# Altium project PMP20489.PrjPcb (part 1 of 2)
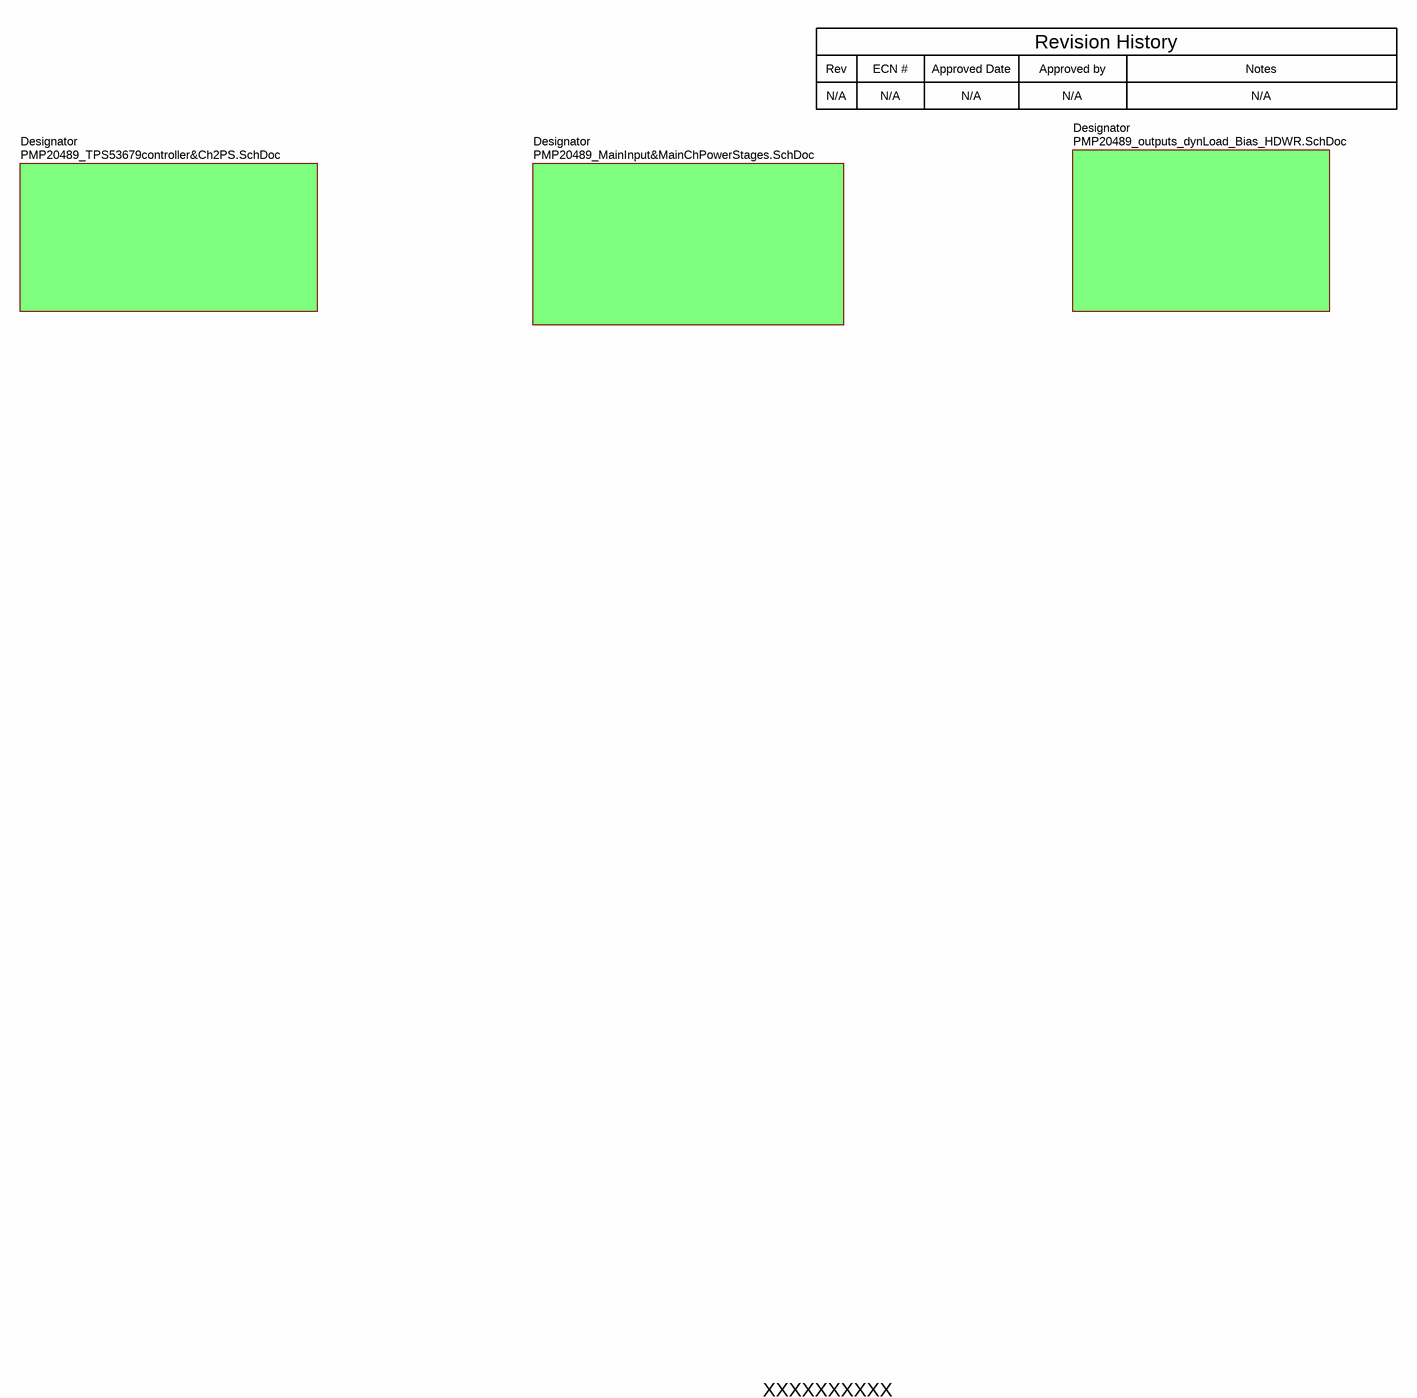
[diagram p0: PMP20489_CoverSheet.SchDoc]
TID: N/A; TechSupport: http://www.ti.com/support; SCH_Rev: A; PRJ_Title: TPS53679 & CSD95490 5+2 4.5-13.2Vin; PRJ_Number: PMP20489; PRJ_Engineer: Josh Mandelcorn; PRJ_Customer: Public Release; PCB_Rev: A; PCB_Layout: Krypton Solutions/RS; EVM_orderable: No; CopyrightYear: 2016
4 sheets, 332 parts. Net scope: flat (ports and power ports of the same name join across sheets).
Board file: PMP20489_PCB.PcbDoc
Sheets:
  PMP20489_CoverSheet.SchDoc
    Designator = PMP20489_TPS53679controller&Ch2PS.SchDoc
    Designator = PMP20489_MainInput&MainChPowerStages.SchDoc
    Designator = PMP20489_outputs_dynLoad_Bias_HDWR.SchDoc

## Sheet PMP20489_CoverSheet.SchDoc
size 431 x 279 mm; Date: Not shown in title block; ApprovedBy: Not shown in title block; CheckedBy: Not shown in title block; Author: Not shown in title block; CompanyName: Not shown in title block; Engineer: Not shown in title block; Organization: Not shown in title block; Address1: Not shown in title block; Address2: Not shown in title block; Address3: Not shown in title block; Address4: Not shown in title block; DocumentNumber: 1; Revision: Use project parameter SCH_Rev; SheetNumber: 1; SheetTotal: 4; PageSetup: Record=PageOptions¦CenterHorizontal=True¦CenterVertical=True¦PrintScale=1.00¦XCorrection=1.00¦YCorrection=1.00¦PrintKind=0¦BorderSize=5000000¦LeftOffset=0¦BottomOffset=0¦Orientation=2¦PaperLength=1000¦PaperWidth=1000¦Scale=100¦PaperSource=15¦PrintQuality=600¦MediaType=1¦DitherType=10¦PaperKind=Letter¦PrintScaleMode=1

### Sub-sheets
Designator = PMP20489_TPS53679controller&Ch2PS.SchDoc: no entries
Designator = PMP20489_MainInput&MainChPowerStages.SchDoc: no entries
Designator = PMP20489_outputs_dynLoad_Bias_HDWR.SchDoc: no entries

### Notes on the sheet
- Rev
- N/A
- ECN #
- Approved Date
- Approved by
- Revision History
- Notes
- XXXXXXXXXX

## Sheet PMP20489_TPS53679controller&Ch2PS.SchDoc
size 431 x 279 mm; Date: Not shown in title block; ApprovedBy: Not shown in title block; CheckedBy: Not shown in title block; Author: Not shown in title block; CompanyName: Not shown in title block; Engineer: Not shown in title block; Organization: Not shown in title block; Address1: Not shown in title block; Address2: Not shown in title block; Address3: Not shown in title block; Address4: Not shown in title block; DocumentNumber: 2; Revision: Use project parameter SCH_Rev; SheetNumber: 2; SheetTotal: 4; PageSetup: Record=PageOptions¦CenterHorizontal=True¦CenterVertical=True¦PrintScale=1.00¦XCorrection=1.00¦YCorrection=1.00¦PrintKind=0¦BorderSize=5000000¦LeftOffset=0¦BottomOffset=0¦Orientation=2¦PaperLength=1000¦PaperWidth=1000¦Scale=100¦PaperSource=15¦PrintQuality=600¦MediaType=1¦DitherType=10¦PaperKind=Letter¦PrintScaleMode=1
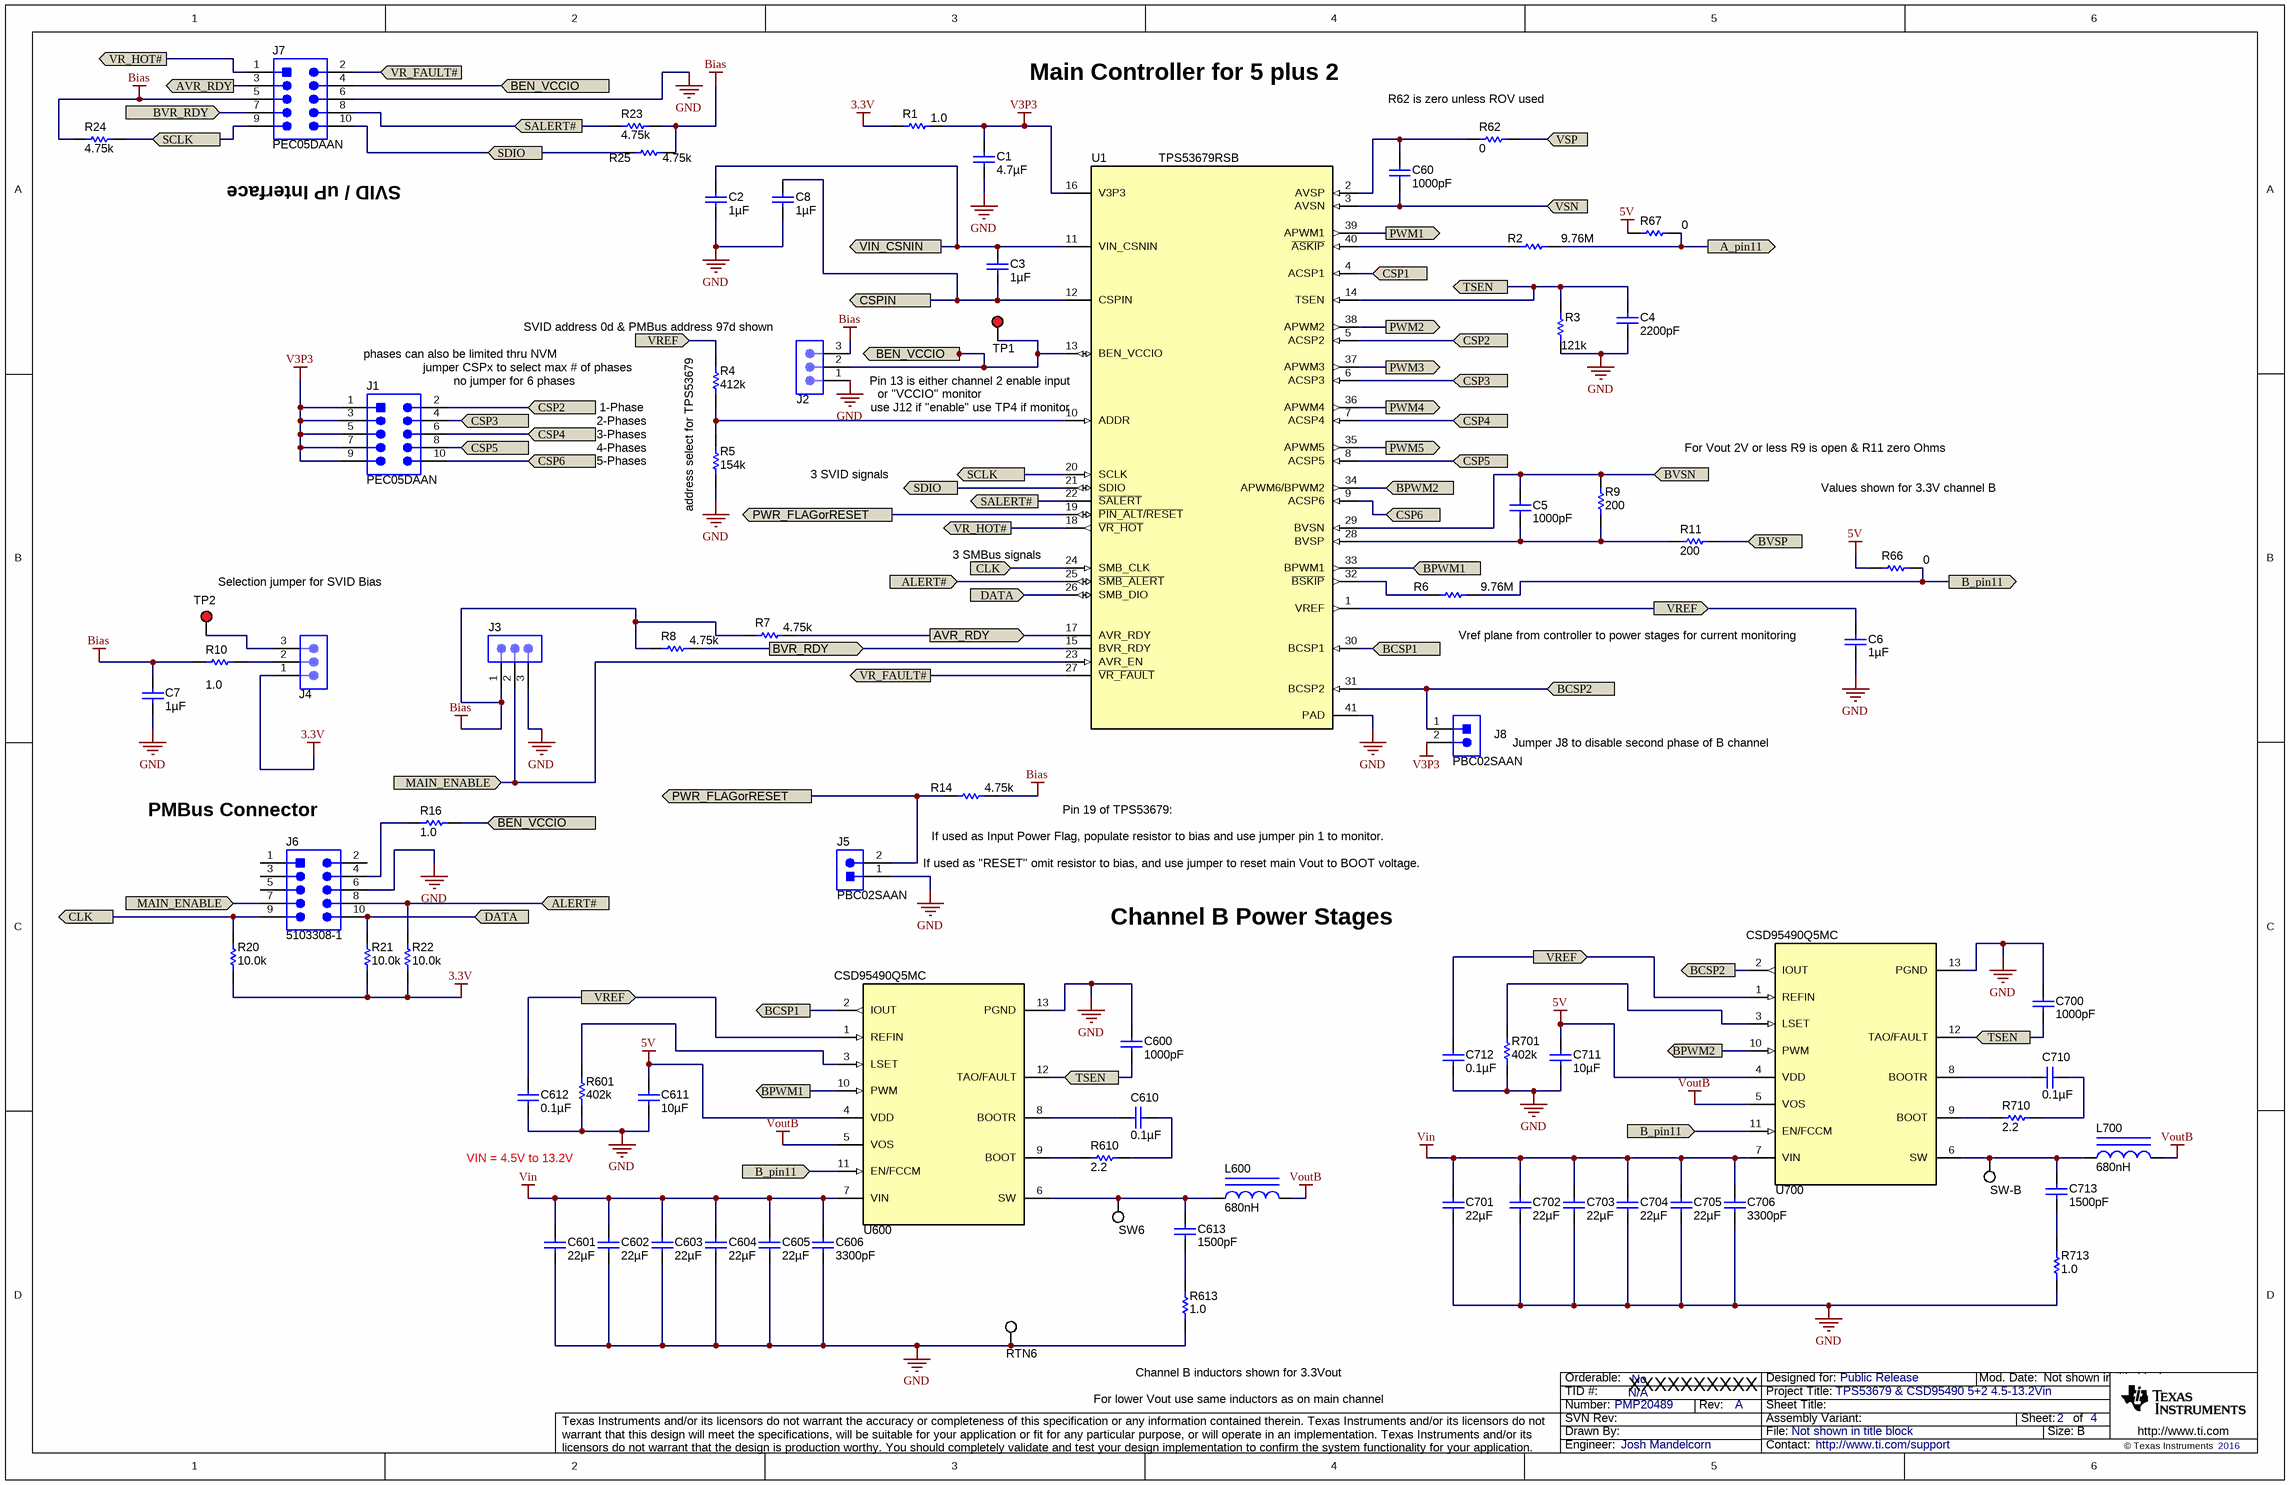
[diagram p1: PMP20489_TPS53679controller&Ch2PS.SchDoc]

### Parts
C1  ValueDisplayed: 4.7µF  [0402]  (hidden comment: GRM155R61A475M)
C2  ValueDisplayed: 1µF  [0603]  (hidden comment: C1608X5R1E105K080AC)
C3  ValueDisplayed: 1µF  [0402]  (hidden comment: C1005X7S1A105K050BC)
C4  ValueDisplayed: 2200pF  [0402]  (hidden comment: C1005X7R1H222K)
C5  ValueDisplayed: 1000pF  [0402L]  (hidden comment: C1005X7R1H102K)
C6  ValueDisplayed: 1µF  [0402]  (hidden comment: C1005X7S1A105K050BC)
C7  ValueDisplayed: 1µF  [0603]  (hidden comment: C1608X5R1E105K080AC)
C8  ValueDisplayed: 1µF  [0603]  (hidden comment: C1608X5R1E105K080AC)
C60  ValueDisplayed: 1000pF  [0402]  (hidden comment: C1005X7R1H102K)
C600  ValueDisplayed: 1000pF  [0402]  (hidden comment: C1005C0G1E102J)
C601  ValueDisplayed: 22µF  [1210]  (hidden comment: C3225X5R1C226M)
C602  ValueDisplayed: 22µF  [1210]  (hidden comment: C3225X5R1C226M)
C603  ValueDisplayed: 22µF  [1210]  (hidden comment: C3225X5R1C226M)
C604  ValueDisplayed: 22µF  [1210]  (hidden comment: C3225X5R1C226M)
C605  ValueDisplayed: 22µF  [1210]  (hidden comment: C3225X5R1C226M)
C606  ValueDisplayed: 3300pF  [0402]  (hidden comment: C1005X7R1H332K)
C610  ValueDisplayed: 0.1µF  [0402]  (hidden comment: GRM155R61E104KA87D)
C611  ValueDisplayed: 10µF  [0603L]  (hidden comment: C0603C106M9PACTU)
C612  ValueDisplayed: 0.1µF  [0402]  (hidden comment: GRM155R61C104KA88D)
C613  ValueDisplayed: 1500pF  [0805_HV]  (hidden comment: 08051C152KAT2A)
C700  ValueDisplayed: 1000pF  [0402]  (hidden comment: C1005C0G1E102J)
C701  ValueDisplayed: 22µF  [1210]  (hidden comment: C3225X5R1C226M)
C702  ValueDisplayed: 22µF  [1210]  (hidden comment: C3225X5R1C226M)
C703  ValueDisplayed: 22µF  [1210]  (hidden comment: C3225X5R1C226M)
C704  ValueDisplayed: 22µF  [1210]  (hidden comment: C3225X5R1C226M)
C705  ValueDisplayed: 22µF  [1210]  (hidden comment: C3225X5R1C226M)
C706  ValueDisplayed: 3300pF  [0402]  (hidden comment: C1005X7R1H332K)
C710  ValueDisplayed: 0.1µF  [0402]  (hidden comment: GRM155R61E104KA87D)
C711  ValueDisplayed: 10µF  [0603L]  (hidden comment: C0603C106M9PACTU)
C712  ValueDisplayed: 0.1µF  [0402]  (hidden comment: GRM155R61C104KA88D)
C713  ValueDisplayed: 1500pF  [0805_HV]  (hidden comment: 08051C152KAT2A)
J1  PEC05DAAN  [CONN_PEC05DAAN]
J2  PBC03SAAN  [PBC03SAAN]  (value not drawn)
J3  PBC03SAAN  [PBC03SAAN]  (value not drawn)
J4  PBC03SAAN  [PBC03SAAN]  (value not drawn)
J5  PBC02SAAN  [Sullins_PBC02SAAN]
J6  5103308-1  [CONN_5103308-1]
J7  PEC05DAAN  [CONN_PEC05DAAN]
J8  PBC02SAAN  [Sullins_PBC02SAAN]
L600  ValueDisplayed: 680nH  [XAL1010]  (hidden comment: XAL1010-681MEB)
L700  ValueDisplayed: 680nH  [XAL1010]  (hidden comment: XAL1010-681MEB)
R1  ValueDisplayed: 1.0  [0402]  (hidden comment: CRCW04021R00JNED)
R2  ValueDisplayed: 9.76M  [0402]  (hidden comment: CRCW04029M76FKED)
R3  ValueDisplayed: 121k  [0402]  (hidden comment: CRCW0402121KFKED)
R4  ValueDisplayed: 412k  [0402]  (hidden comment: CRCW0402412KFKED)
R5  ValueDisplayed: 154k  [0402]  (hidden comment: CRCW0402154KFKED)
R6  ValueDisplayed: 9.76M  [0402]  (hidden comment: CRCW04029M76FKED)
R7  ValueDisplayed: 4.75k  [0402]  (hidden comment: CRCW04024K75FKED)
R8  ValueDisplayed: 4.75k  [0402]  (hidden comment: CRCW04024K75FKED)
R9  ValueDisplayed: 200  [0402]  (hidden comment: CRCW0402200RFKED)
R10  ValueDisplayed: 1.0  [0402]  (hidden comment: CRCW04021R00JNED)
R11  ValueDisplayed: 200  [0402]  (hidden comment: CRCW0402200RFKED)
R14  ValueDisplayed: 4.75k  [0402]  (hidden comment: CRCW04024K75FKED)
R16  value 1.0  [0402]  (hidden comment: CRCW04021R00JNED)
R20  value 10.0k  [0402]  (hidden comment: CRCW040210K0FKED)
R21  value 10.0k  [0402]  (hidden comment: CRCW040210K0FKED)
R22  value 10.0k  [0402]  (hidden comment: CRCW040210K0FKED)
R23  ValueDisplayed: 4.75k  [0402]  (hidden comment: CRCW04024K75FKED)
R24  ValueDisplayed: 4.75k  [0402]  (hidden comment: CRCW04024K75FKED)
R25  ValueDisplayed: 4.75k  [0402]  (hidden comment: CRCW04024K75FKED)
R62  ValueDisplayed: 0  [0402]  (hidden comment: CRCW04020000Z0ED)
R66  ValueDisplayed: 0  [0402]  (hidden comment: RC0402JR-070RL)
R67  ValueDisplayed: 0  [0402]  (hidden comment: RC0402JR-070RL)
R601  ValueDisplayed: 402k  [0402]  (hidden comment: CRCW0402402KFKED)
R610  value 2.2  [0402]  (hidden comment: CRCW04022R20JNED)
R613  value 1.0  [1206]  (hidden comment: CRM1206-JW-1R0ELF)
R701  ValueDisplayed: 402k  [0402]  (hidden comment: CRCW0402402KFKED)
R710  value 2.2  [0402]  (hidden comment: CRCW04022R20JNED)
R713  value 1.0  [1206]  (hidden comment: CRM1206-JW-1R0ELF)
RTN6  5016  [Testpoint_Keystone_Compact]  (value not drawn)
SW6  5015  [Testpoint_Keystone_Miniature]  (value not drawn)
SW-B  5015  [Testpoint_Keystone_Miniature]  (value not drawn)
TP1  5000  [Keystone5000]  (value not drawn)
TP2  5000  [Keystone5000]  (value not drawn)
U1  TPS53679RSB  [RSB0040E]
U600  CSD95490Q5MC  [DMC0012A]
U700  CSD95490Q5MC  [DMC0012A]

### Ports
A_pin11, ALERT#, ALERT# (in), AVR_RDY, AVR_RDY (out), B_pin11, BCSP1, BCSP1 (out), BCSP2, BCSP2 (out), BEN_VCCIO, BPWM1, BPWM2, BVR_RDY, BVR_RDY (out), BVSN, BVSP, CLK, CSP1 (in), CSP2, CSP2 (in), CSP3, CSP3 (in), CSP4, CSP5, CSP6, CSPIN, DATA, DATA (in), MAIN_ENABLE, MAIN_ENABLE (in), PWM1 (out), PWM2 (out), PWM3 (out), PWM4 (out), PWM5 (out), PWR_FLAGorRESET, SALERT#, SCLK, SDIO, TSEN, VIN_CSNIN, VR_FAULT#, VR_HOT#, VREF, VSN (in), VSP (in)

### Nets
3.3V: J4.1 R1.1 R20.2 R21.2 R22.2
5V: C611.1 C711.1 R66.1 R67.1 U600.4(VDD) U700.4(VDD)
Bias: C7.1 J2.3 J3.1 J7.5 R7.2 R8.2 R10.1 R14.1 R23.1 R24.2 R25.1
GND: C1.2 C2.2 C4.2 C6.2 C7.2 C8.2 C600.1 C601.2 C602.2 C603.2 C604.2 C605.2 C606.2 C611.2 C612.2 C700.1 C701.2 C702.2 C703.2 C704.2 C705.2 C706.2 C711.2 C712.2 J2.1 J3.3 J5.1 J6.6 J7.6 R3.1 R5.1 R601.1 R613.1 R701.1 R713.1 RTN6.1 U1.41(PAD) U600.13(PGND) U700.13(PGND)
V3P3: C1.1 J1.1 J1.3 J1.5 J1.7 J1.9 J8.2 R1.2 U1.16(V3P3)
Vin: C601.1 C602.1 C603.1 C604.1 C605.1 C606.1 C701.1 C702.1 C703.1 C704.1 C705.1 C706.1 U600.7(VIN) U700.7(VIN)
VoutB: L600.2 L700.2 U600.5(VOS) U700.5(VOS)
A_pin11: R2.2 R67.2 ; port A_pin11
ALERT#: J6.8 R22.1 U1.25(~{SMB_ALERT}) ; port ALERT#
AVR_RDY: J7.3 R7.1 U1.17(AVR_RDY) ; port AVR_RDY
B_pin11: R6.2 R66.2 U600.11(EN/FCCM) U700.11(EN/FCCM) ; port B_pin11
BCSP1: U1.30(BCSP1) U600.2(IOUT) ; port BCSP1
BCSP2: J8.1 U1.31(BCSP2) U700.2(IOUT) ; port BCSP2
BEN_VCCIO: J2.2 J7.4 R16.2 TP1.1 U1.13(BEN_VCCIO) ; port BEN_VCCIO
BPWM1: U1.33(BPWM1) U600.10(PWM) ; port BPWM1
BPWM2: U1.34(APWM6/BPWM2) U700.10(PWM) ; port BPWM2
BVR_RDY: J7.7 R8.1 U1.15(BVR_RDY) ; port BVR_RDY
BVSN: C5.1 R9.2 U1.29(BVSN) ; port BVSN
BVSP: R11.2 ; port BVSP
CLK: J6.9 R20.1 U1.24(SMB_CLK) ; port CLK
CSP1: U1.4(ACSP1) ; port CSP1
CSP2: J1.2 U1.5(ACSP2) ; port CSP2
CSP3: J1.4 U1.6(ACSP3) ; port CSP3
CSP4: J1.6 U1.7(ACSP4) ; port CSP4
CSP5: J1.8 U1.8(ACSP5) ; port CSP5
CSP6: J1.10 U1.9(ACSP6) ; port CSP6
CSPIN: C3.2 C8.1 U1.12(CSPIN) ; port CSPIN
DATA: J6.10 R21.1 U1.26(SMB_DIO) ; port DATA
MAIN_ENABLE: J3.2 J6.7 U1.23(AVR_EN) ; port MAIN_ENABLE
PWM1: U1.39(APWM1) ; port PWM1
PWM2: U1.38(APWM2) ; port PWM2
PWM3: U1.37(APWM3) ; port PWM3
PWM4: U1.36(APWM4) ; port PWM4
PWM5: U1.35(APWM5) ; port PWM5
PWR_FLAGorRESET: J5.2 R14.2 U1.19(~{PIN_ALT}/~{RESET}) ; port PWR_FLAGorRESET
SALERT#: J7.8 R23.2 U1.22(~{SALERT}) ; port SALERT#
SCLK: J7.9 R24.1 U1.20(SCLK) ; port SCLK
SDIO: J7.10 R25.2 U1.21(SDIO) ; port SDIO
TSEN: C4.1 C600.2 C700.2 R3.2 U1.14(TSEN) U600.12(TAO/FAULT) U700.12(TAO/FAULT) ; port TSEN
VIN_CSNIN: C2.1 C3.1 U1.11(VIN_CSNIN) ; port VIN_CSNIN
VR_FAULT#: J7.2 U1.27(~{VR_FAULT}) ; port VR_FAULT#
VR_HOT#: J7.1 U1.18(~{VR_HOT}) ; port VR_HOT#
VREF: C6.1 C612.1 C712.1 R4.2 U1.1(VREF) U600.1(REFIN) U700.1(REFIN) ; port VREF
VSN: C60.2 U1.3(AVSN) ; port VSN
VSP: R62.2 ; port VSP
NetC5_2: C5.2 R9.1 R11.1 U1.28(BVSP)
NetC60_1: C60.1 R62.1 U1.2(AVSP)
NetC610_1: C610.1 U600.8(BOOTR)
NetC610_2: C610.2 R610.1
NetC613_1: C613.1 L600.1 SW6.1 U600.6(SW)
NetC613_2: C613.2 R613.2
NetC710_1: C710.1 U700.8(BOOTR)
NetC710_2: C710.2 R710.1
NetC713_1: C713.1 L700.1 SW-B.1 U700.6(SW)
NetC713_2: C713.2 R713.2
NetJ4_2: J4.2 R10.2
NetJ4_3: J4.3 TP2.1
NetJ6_4: J6.4 R16.1
NetR2_1: R2.1 U1.40(~{ASKIP})
NetR4_1: R4.1 R5.2 U1.10(ADDR)
NetR6_1: R6.1 U1.32(~{BSKIP})
NetR601_2: R601.2 U600.3(LSET)
NetR610_2: R610.2 U600.9(BOOT)
NetR701_2: R701.2 U700.3(LSET)
NetR710_2: R710.2 U700.9(BOOT)

Not connected (* = marked no-connect by the designer): J6 1 2 3 5

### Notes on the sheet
- Main Controller for 5 plus 2
- (near R62) R62 is zero unless ROV used
- SVID / uP Interface
- (near J1) phases can also be limited thru NVM
- (near J1) jumper CSPx to select max # of phases
- (near R4) SVID address 0d & PMBus address 97d shown
- (near J1) no jumper for 6 phases
- 3-Phases
- 2-Phases
- 1-Phase
- address select for TPS53679
- or "VCCIO" monitor
- (near U1) Pin 13 is either channel 2 enable input
- (near U1) use J12 if "enable" use TP4 if monitor
- 4-Phases
- 5-Phases
- 3 SVID signals
- For Vout 2V or less R9 is open & R11 zero Ohms
- Values shown for 3.3V channel B
- (near U1) 3 SMBus signals
- (near TP2) Selection jumper for SVID Bias
- Vref plane from controller to power stages for current monitoring
- (near J8) Jumper J8 to disable second phase of B channel
- (near J6) PMBus Connector
- Pin 19 of TPS53679:
- If used as Input Power Flag, populate resistor to bias and use jumper pin 1 to monitor.
- (near J5) If used as "RESET" omit resistor to bias, and use jumper to reset main Vout to BOOT voltage.
- Channel B Power Stages
- VIN = 4.5V to 13.2V
- (near R613) Channel B inductors shown for 3.3Vout
- XXXXXXXXXX
- For lower Vout use same inductors as on main channel

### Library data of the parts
C1 = GRM155R61A475M: CAP, CERM, 4.7 µF, 10 V, +/- 20%, X5R, 0402; Manufacturer: MuRata; Polarized: N; CompType: Capacitor; Value: 4.7uF; U/M: EA; Cap_F: 0.0000047; Tolerance_%: 20; Value1: Unknown; VDC_V: 10; Value2: 10V; TaMin_C: -55; TaMax_C: 85; SizeArea_mm2: 0.5; SizeAreaWB_mm2: 3; SizeX_mm: 1; SizeZ_mm: 0.6; AEC Category: Q200
C2 C7 C8 = C1608X5R1E105K080AC: CAP, CERM, 1 µF, 25 V, +/- 10%, X5R, 0603; Manufacturer: TDK; Polarized: N; CompType: Capacitor; Value: 1uF; U/M: EA; Cap_F: 0.000001; Tolerance_%: 10; Value1: Unknown; VDC_V: 25; Value2: 25V; TaMin_C: -55; TaMax_C: 85; SizeArea_mm2: 1.28; SizeAreaWB_mm2: 4.68; SizeX_mm: 1.6; SizeY_mm: 0.8; SizeZ_mm: 1; AEC Category: Q200
C3 C6 = C1005X7S1A105K050BC: CAP, CERM, 1 µF, 10 V, +/- 10%, X7S, 0402; Manufacturer: TDK; Polarized: N; CompType: Capacitor; Value: 1uF; U/M: EA; Cap_F: 0.000001; Tolerance_%: 10; ESR_ohm: 0.011416; Value1: 0.011416 ohm; Value2: 10V; IRMS_A: 1.483; TaMin_C: -55; TaMax_C: 125; SizeArea_mm2: 0.5; SizeAreaWB_mm2: 3; SizeX_mm: 1; SizeZ_mm: 0.6; AEC Category: Q200
C4 = C1005X7R1H222K: CAP, CERM, 2200 pF, 50 V, +/- 10%, X7R, 0402; Manufacturer: TDK; Polarized: N; CompType: Capacitor; Value: 2200pF; U/M: EA; Cap_F: 0.0000000022; Tolerance_%: 10; ESR_ohm: 0.1433; Value1: 0.1433 ohm; VDC_V: 50; Value2: 50V; TaMin_C: -55; TaMax_C: 125
C5 = C1005X7R1H102K: CAP, CERM, 1000 pF, 50 V, +/- 10%, X7R, 0402; Manufacturer: TDK; Polarized: N; CompType: Capacitor; Value: 1000pF; U/M: EA; Cap_F: 0.000000001; Tolerance_%: 10; ESR_ohm: 0.2381; Value1: 0.2381 ohm; VDC_V: 50; Value2: 50V; TaMin_C: -55; TaMax_C: 125; Cap_Case: 0402
C60 = C1005X7R1H102K: CAP, CERM, 1000 pF, 50 V, +/- 10%, X7R, 0402; Manufacturer: TDK; Polarized: N; CompType: Capacitor; Value: 1000pF; U/M: EA; Cap_F: 0.000000001; Tolerance_%: 10; ESR_ohm: 0.2381; Value1: 0.2381 ohm; VDC_V: 50; Value2: 50V; TaMin_C: -55; TaMax_C: 125
C600 C700 = C1005C0G1E102J: CAP, CERM, 1000 pF, 25 V, +/- 5%, C0G/NP0, 0402; Manufacturer: TDK; Polarized: N; CompType: Capacitor; Value: 1000pF; U/M: EA; Cap_F: 0.000000001; Tolerance_%: 5; Value1: Unknown; VDC_V: 25; Value2: 25V; TaMin_C: -55; TaMax_C: 125
C601-C605 C701-C705 = C3225X5R1C226M: CAP, CERM, 22 µF, 16 V, +/- 20%, X5R, 1210; Manufacturer: TDK; Polarized: N; CompType: Capacitor; Value: 22uF; U/M: EA; Cap_F: 0.000022; Tolerance_%: 20; ESR_ohm: 0.002; Value1: 0.002 ohm; VDC_V: 16; Value2: 16V; IRMS_A: 3.5; TaMin_C: -55; TaMax_C: 85
C606 C706 = C1005X7R1H332K: CAP, CERM, 3300 pF, 50 V, +/- 10%, X7R, 0402; Manufacturer: TDK; Polarized: N; CompType: Capacitor; Value: 3300pF; U/M: EA; Cap_F: 0.0000000033; Tolerance_%: 10; ESR_ohm: 0.12; Value1: 0.12 ohm; VDC_V: 50; Value2: 50V; TaMin_C: -55; TaMax_C: 125
C610 C710 = GRM155R61E104KA87D: CAP, CERM, 0.1 µF, 25 V, +/- 10%, X5R, 0402; Manufacturer: MuRata; Polarized: N; CompType: Capacitor; Value: 0.1uF; U/M: EA; Cap_F: 0.0000001; Tolerance_%: 10; Value1: Unknown; VDC_V: 25; Value2: 25V; TaMin_C: -55; TaMax_C: 85; SizeArea_mm2: 0.5; SizeAreaWB_mm2: 3; SizeX_mm: 1; SizeZ_mm: 0.6; AEC Category: Q200
C611 C711 = C0603C106M9PACTU: CAP, CERM, 10 µF, 6.3 V, +/- 20%, X5R, 0603; Manufacturer: Kemet; Polarized: N; CompType: Capacitor; Value: 10uF; U/M: EA; Cap_F: 0.00001; Tolerance_%: 20; ESR_ohm: 0.004; Value1: 0.004 ohm; VDC_V: 6.3; Value2: 6.3V; IRMS_A: 8.9; TaMin_C: -55; TaMax_C: 85; Cap_Case: 0603; SizeArea_mm2: 1.28; SizeAreaWB_mm2: 4.68; SizeX_mm: 1.6; SizeY_mm: 0.8; SizeZ_mm: 1; AEC Category: Q200
C612 C712 = GRM155R61C104KA88D: CAP, CERM, 0.1 µF, 16 V, +/- 10%, X5R, 0402; Manufacturer: MuRata; Polarized: N; CompType: Capacitor; Value: 0.1uF; U/M: EA; Cap_F: 0.0000001; Tolerance_%: 10; Value1: Unknown; VDC_V: 16; Value2: 16V; TaMin_C: -55; TaMax_C: 85; SizeArea_mm2: 0.5; SizeAreaWB_mm2: 3; SizeX_mm: 1; SizeZ_mm: 0.6; AEC Category: Q200
C613 C713 = 08051C152KAT2A: CAP, CERM, 1500 pF, 100 V, +/- 10%, X7R, 0805; Manufacturer: AVX; Polarized: N; CompType: Capacitor; Value: 1500pF; U/M: EA; Cap_F: 0.0000000015; Tolerance_%: 10; ESR_ohm: 0.229; Value1: 0.229 ohm; VDC_V: 100; Value2: 100V; TaMin_C: -55; TaMax_C: 125; Cap_Case: 0805; SizeArea_mm2: 2.5; SizeAreaWB_mm2: 6.75; SizeX_mm: 2; SizeY_mm: 1.25; SizeZ_mm: 1.45; AEC Category: Q200
J1 J7 = PEC05DAAN: Header, 100mil, 5x2, Tin, TH; Manufacturer: Sullins Connector Solutions; SymbolCreator: a0412235; Pitch_mm: 2.54; Gender: Male; Shrouded: N; Row_Count: 2; Current_A: 3; Voltage_V: 1800; Cert_UL: Y
J2-J4 = PBC03SAAN: Header, 100mil, 3x1, Gold, TH; Manufacturer: Sullins Connector Solutions
J5 J8 = PBC02SAAN: Header, 100mil, 2x1, Gold, TH; Manufacturer: Sullins Connector Solutions; SymbolCreator: a0412235; Pitch_mm: 2.54; Gender: Male; Shrouded: N; Row_Count: 1; Current_A: 3; Voltage_V: 1800; Cert_UL: Y
J6 = 5103308-1: Header (shrouded), 100mil, 5x2, Gold, TH; Manufacturer: TE Connectivity; SymbolCreator: a0412235
L600 L700 = XAL1010-681MEB: Inductor, Shielded, Composite, 680 nH, 36 A, 0.00087 ohm, SMD; Manufacturer: Coilcraft; Value: 680nH; Ind_H: 680.0E-9; Imax_A: 36; Irms: 36A @ 20C rise; Isat: 62A @ 30% inductance drop; Value2: 36A; AEC Category: Q200; AEC Qualified: N; SizeAreaWB_mm2: 159.6; SizeArea_mm2: 113; SizeX_mm: 11.3; SizeY_mm: 10; Green_Lifecycle: Not Set; Green_REACh: Incomplete
R1 R10 = CRCW04021R00JNED: RES, 1.0, 5%, 0.063 W, 0402; Manufacturer: Vishay-Dale; CompType: Resistor; Value: 1.0; Res_ohm: 1; Value_Code: 1R00; Tolerance_%: 5; Power_W: 0.063; Value2: 0.063W; VDC_V: 50; TempCo: 200 ppm/C; EIA_Code: E24; U/M: EA; SizeArea_mm2: 0.5; SizeZ_mm: 0.6; AEC Category: Q200
R2 R6 = CRCW04029M76FKED: RES, 9.76 M, 1%, 0.063 W, 0402; Manufacturer: Vishay-Dale; CompType: Resistor; Res_ohm: 9760000; Value_Code: 9M76; Tolerance_%: 1; Power_W: 0.063; Value2: 0.063W; VDC_V: 50; TempCo: 100 ppm/C; EIA_Code: E96; U/M: EA; Value: 9.76Meg; SizeArea_mm2: 0.5; SizeZ_mm: 0.6; AEC Category: Q200
R3 = CRCW0402121KFKED: RES, 121 k, 1%, 0.063 W, 0402; Manufacturer: Vishay-Dale; CompType: Resistor; Value: 121k; Res_ohm: 121000; Tolerance_%: 1; Power_W: 0.063; Value2: 0.063W; VDC_V: 50; TempCo: 100 ppm/C; EIA_Code: E96; U/M: EA; SizeArea_mm2: 0.5; SizeZ_mm: 0.6; AEC Category: Q200
R4 = CRCW0402412KFKED: RES, 412 k, 1%, 0.063 W, 0402; Manufacturer: Vishay-Dale; CompType: Resistor; Value: 412k; Res_ohm: 412000; Tolerance_%: 1; Power_W: 0.063; Value2: 0.063W; VDC_V: 50; TempCo: 100 ppm/C; EIA_Code: E96; U/M: EA; SizeArea_mm2: 0.5; SizeZ_mm: 0.6; AEC Category: Q200
R5 = CRCW0402154KFKED: RES, 154 k, 1%, 0.063 W, 0402; Manufacturer: Vishay-Dale; CompType: Resistor; Value: 154k; Res_ohm: 154000; Tolerance_%: 1; Power_W: 0.063; Value2: 0.063W; VDC_V: 50; TempCo: 100 ppm/C; EIA_Code: E96; U/M: EA; SizeArea_mm2: 0.5; SizeZ_mm: 0.6; AEC Category: Q200
R7 R8 R14 R23-R25 = CRCW04024K75FKED: RES, 4.75 k, 1%, 0.063 W, 0402; Manufacturer: Vishay-Dale; CompType: Resistor; Value: 4.75k; Res_ohm: 4750; Value_Code: 4k75; Tolerance_%: 1; Power_W: 0.063; Value2: 0.063W; VDC_V: 50; TempCo: 100 ppm/C; EIA_Code: E96; U/M: EA; SizeArea_mm2: 0.5; SizeZ_mm: 0.6; AEC Category: Q200
R9 R11 = CRCW0402200RFKED: RES, 200, 1%, 0.063 W, 0402; Manufacturer: Vishay-Dale; CompType: Resistor; Value_Code: 200R; Tolerance_%: 1; Power_W: 0.063; Value2: 0.063W; VDC_V: 50; TempCo: 100 ppm/C; EIA_Code: E96; U/M: EA; Value: 200; SizeArea_mm2: 0.5; SizeZ_mm: 0.6; AEC Category: Q200
R16 = CRCW04021R00JNED: RES, 1.0, 5%, 0.063 W, 0402; Manufacturer: Vishay-Dale; CompType: Resistor; Res_ohm: 1; Value_Code: 1R00; Tolerance_%: 5; Power_W: 0.063; Value2: 0.063W; VDC_V: 50; TempCo: 200 ppm/C; EIA_Code: E24; U/M: EA; SizeArea_mm2: 0.5; SizeZ_mm: 0.6; AEC Category: Q200
R20-R22 = CRCW040210K0FKED: RES, 10.0 k, 1%, 0.063 W, 0402; Manufacturer: Vishay-Dale; CompType: Resistor; Res_ohm: 10000; Value_Code: 10k0; Tolerance_%: 1; Power_W: 0.063; Value2: 0.063W; VDC_V: 50; TempCo: 100 ppm/C; EIA_Code: E96; U/M: EA; SizeArea_mm2: 0.5; SizeZ_mm: 0.6; AEC Category: Q200
R62 = CRCW04020000Z0ED: RES, 0, 5%, 0.063 W, 0402; Manufacturer: Vishay-Dale; CompType: Resistor; Value: 0; Value_Code: 0000; Tolerance_%: 5; Power_W: 0.063; Value2: 0.063W; VDC_V: 50; TempCo: 200 ppm/C; EIA_Code: E24; U/M: EA; SizeArea_mm2: 0.5; SizeX_mm: 1; SizeZ_mm: 0.6; AEC Category: Q200
R66 R67 = RC0402JR-070RL: RES, 0, 5%, 0.063 W, 0402; Manufacturer: Yageo America; CompType: Resistor; Value_Code: 0000; Tolerance_%: 5; Power_W: 0.063; Value2: 0.063W; VDC_V: 50; TempCo: 200 ppm/C; EIA_Code: E24; U/M: EA; Value: 0; SizeArea_mm2: 0.5; SizeX_mm: 1; SizeZ_mm: 0.6; AEC Category: Q200
R601 R701 = CRCW0402402KFKED: RES, 402 k, 1%, 0.063 W, 0402; Manufacturer: Vishay-Dale; CompType: Resistor; Value: 402k; Res_ohm: 402000; Tolerance_%: 1; Power_W: 0.063; Value2: 0.063W; VDC_V: 50; TempCo: 100 ppm/C; EIA_Code: E96; U/M: EA; SizeArea_mm2: 0.5; SizeZ_mm: 0.6; AEC Category: Q200
R610 R710 = CRCW04022R20JNED: RES, 2.2, 5%, 0.063 W, 0402; Manufacturer: Vishay-Dale; CompType: Resistor; Value_Code: 2R20; Tolerance_%: 5; Power_W: 0.063; Value2: 0.063W; VDC_V: 50; TempCo: 200 ppm/C; EIA_Code: E24; U/M: EA; SizeArea_mm2: 0.5; SizeX_mm: 1; SizeZ_mm: 0.6; AEC Category: Q200
R613 R713 = CRM1206-JW-1R0ELF: RES, 1.0, 5%, 0.5 W, 1206; Manufacturer: Bourns; CompType: Resistor; Res_ohm: 1; Value_Code: 1R00; Tolerance_%: 5; Power_W: 0.5; Value2: 0.5W; TempCo: 150 ppm/C; EIA_Code: E24; U/M: EA; SizeArea_mm2: 5.12; SizeX_mm: 3.2; SizeY_mm: 1.6; SizeZ_mm: 1.35; AEC Category: Q200
RTN6 = 5016: Test Point, Compact, SMT; Manufacturer: Keystone; CompType: Test Point Loop
SW6 SW-B = 5015: Test Point, Miniature, SMT; Manufacturer: Keystone; CompType: Test Point Loop
TP1 TP2 = 5000: Test Point, Miniature, Red, TH; Manufacturer: Keystone; CompType: Test Point Loop; ContactFinish: Silver
U1 = TPS53679RSB: Dual-Channel (6+1 or 5+2 Phases) D-CAP+ Step-Down Multiphase Controller with Non-Volitile Memory and PMBus Interface for VR13 Server VCORE, RSB0040E; Manufacturer: Texas Instruments; SymbolCreator: a0411947; CompType: IC; U/M: EA; SizeArea_mm2: 25; SizeAreaWB_mm2: 49; SizeX_mm: 5; SizeZ_mm: 0.8
U600 U700 = CSD95490Q5MC: Synchronous Buck NexFET Power Stage, DMC0012A; Alternate PartNumber: CSD95490Q5MCT; Manufacturer: Texas Instruments; SymbolCreator: Altium; CompType: IC; U/M: EA; SizeArea_mm2: 30; SizeAreaWB_mm2: 56; SizeX_mm: 5; SizeY_mm: 6; SizeZ_mm: 1.05

## Sheet PMP20489_MainInput&MainChPowerStages.SchDoc
size 431 x 279 mm; Date: Not shown in title block; ApprovedBy: Not shown in title block; CheckedBy: Not shown in title block; Author: Not shown in title block; CompanyName: Not shown in title block; Engineer: Not shown in title block; Organization: Not shown in title block; Address1: Not shown in title block; Address2: Not shown in title block; Address3: Not shown in title block; Address4: Not shown in title block; DocumentNumber: 3; Revision: Use project parameter SCH_Rev; SheetNumber: 3; SheetTotal: 4; PageSetup: Record=PageOptions¦CenterHorizontal=True¦CenterVertical=True¦PrintScale=1.00¦XCorrection=1.00¦YCorrection=1.00¦PrintKind=0¦BorderSize=5000000¦LeftOffset=0¦BottomOffset=0¦Orientation=2¦PaperLength=1000¦PaperWidth=1000¦Scale=100¦PaperSource=15¦PrintQuality=600¦MediaType=1¦DitherType=10¦PaperKind=Letter¦PrintScaleMode=1
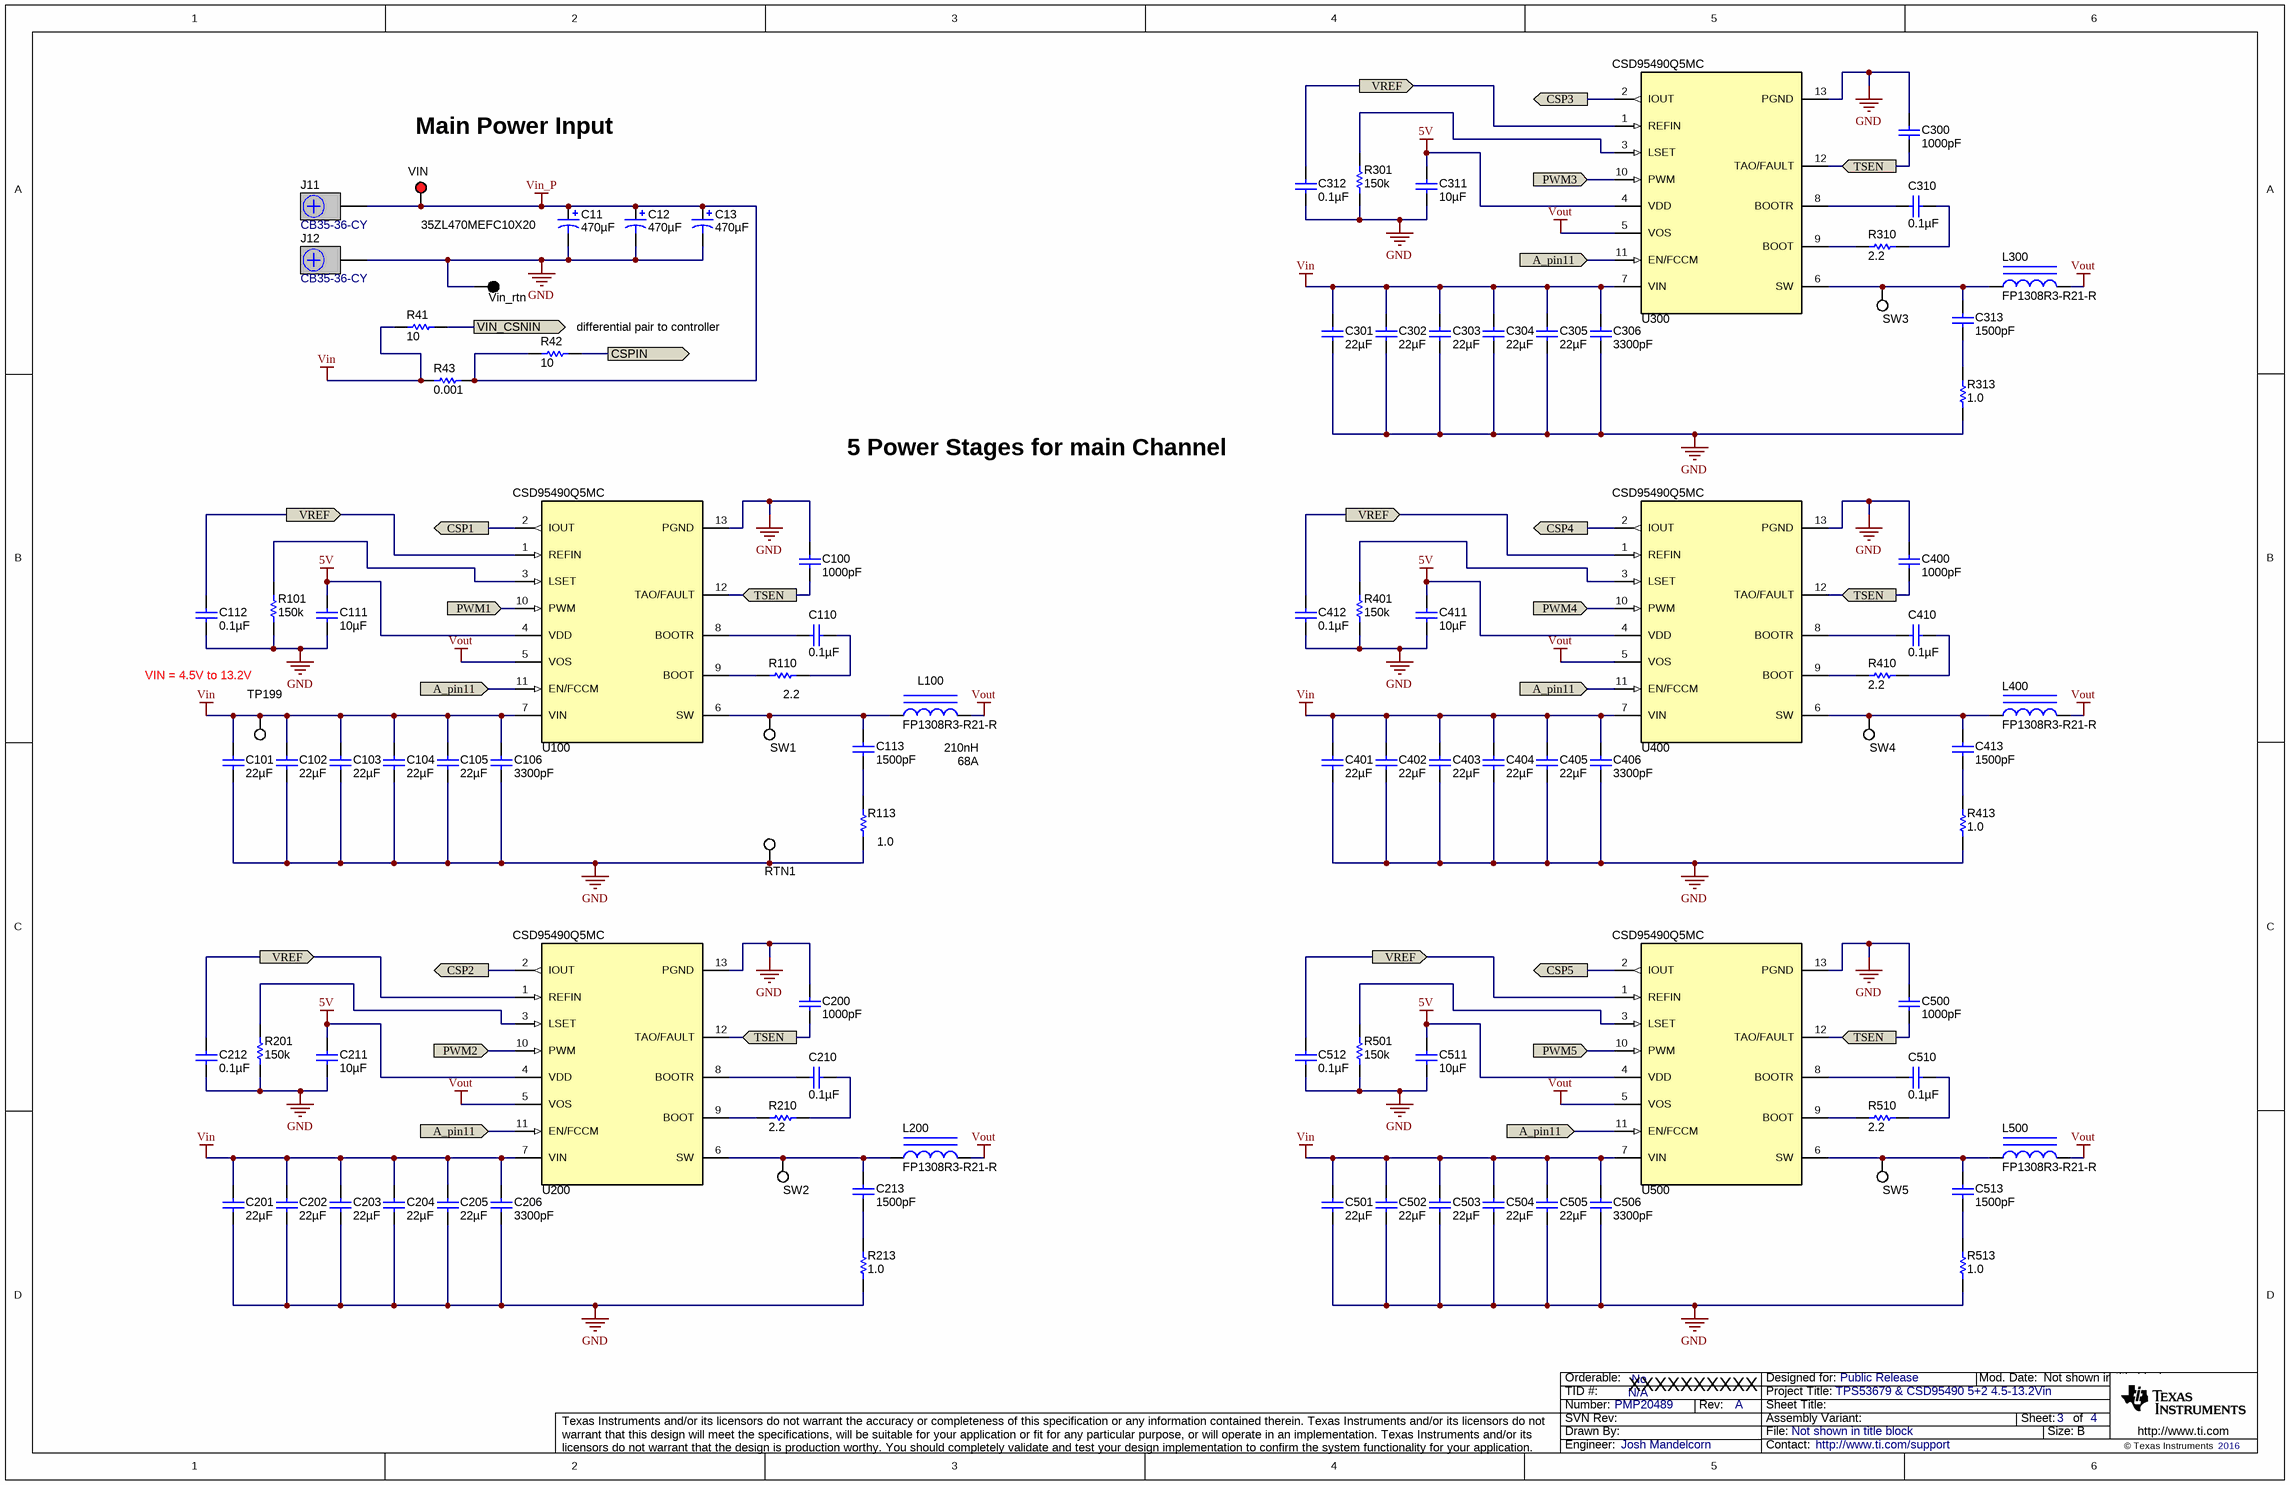
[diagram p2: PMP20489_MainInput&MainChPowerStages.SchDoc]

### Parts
C11  ValueDisplayed: 470µF  [ZL_1000x2000]  (hidden comment: 35ZL470MEFC10X20)
C12  ValueDisplayed: 470µF  [ZL_1000x2000]  (hidden comment: 35ZL470MEFC10X20)
C13  ValueDisplayed: 470µF  [ZL_1000x2000]  (hidden comment: 35ZL470MEFC10X20)
C100  ValueDisplayed: 1000pF  [0402]  (hidden comment: C1005C0G1E102J)
C101  ValueDisplayed: 22µF  [1210]  (hidden comment: C3225X5R1C226M)
C102  ValueDisplayed: 22µF  [1210]  (hidden comment: C3225X5R1C226M)
C103  ValueDisplayed: 22µF  [1210]  (hidden comment: C3225X5R1C226M)
C104  ValueDisplayed: 22µF  [1210]  (hidden comment: C3225X5R1C226M)
C105  ValueDisplayed: 22µF  [1210]  (hidden comment: C3225X5R1C226M)
C106  ValueDisplayed: 3300pF  [0402]  (hidden comment: C1005X7R1H332K)
C110  ValueDisplayed: 0.1µF  [0402]  (hidden comment: GRM155R61E104KA87D)
C111  ValueDisplayed: 10µF  [0603L]  (hidden comment: C0603C106M9PACTU)
C112  ValueDisplayed: 0.1µF  [0402]  (hidden comment: GRM155R61C104KA88D)
C113  ValueDisplayed: 1500pF  [0805_HV]  (hidden comment: 08051C152KAT2A)
C200  ValueDisplayed: 1000pF  [0402]  (hidden comment: C1005C0G1E102J)
C201  ValueDisplayed: 22µF  [1210]  (hidden comment: C3225X5R1C226M)
C202  ValueDisplayed: 22µF  [1210]  (hidden comment: C3225X5R1C226M)
C203  ValueDisplayed: 22µF  [1210]  (hidden comment: C3225X5R1C226M)
C204  ValueDisplayed: 22µF  [1210]  (hidden comment: C3225X5R1C226M)
C205  ValueDisplayed: 22µF  [1210]  (hidden comment: C3225X5R1C226M)
C206  ValueDisplayed: 3300pF  [0402]  (hidden comment: C1005X7R1H332K)
C210  ValueDisplayed: 0.1µF  [0402]  (hidden comment: GRM155R61E104KA87D)
C211  ValueDisplayed: 10µF  [0603L]  (hidden comment: C0603C106M9PACTU)
C212  ValueDisplayed: 0.1µF  [0402]  (hidden comment: GRM155R61C104KA88D)
C213  ValueDisplayed: 1500pF  [0805_HV]  (hidden comment: 08051C152KAT2A)
C300  ValueDisplayed: 1000pF  [0402]  (hidden comment: C1005C0G1E102J)
C301  ValueDisplayed: 22µF  [1210]  (hidden comment: C3225X5R1C226M)
C302  ValueDisplayed: 22µF  [1210]  (hidden comment: C3225X5R1C226M)
C303  ValueDisplayed: 22µF  [1210]  (hidden comment: C3225X5R1C226M)
C304  ValueDisplayed: 22µF  [1210]  (hidden comment: C3225X5R1C226M)
C305  ValueDisplayed: 22µF  [1210]  (hidden comment: C3225X5R1C226M)
C306  ValueDisplayed: 3300pF  [0402]  (hidden comment: C1005X7R1H332K)
C310  ValueDisplayed: 0.1µF  [0402]  (hidden comment: GRM155R61E104KA87D)
C311  ValueDisplayed: 10µF  [0603L]  (hidden comment: C0603C106M9PACTU)
C312  ValueDisplayed: 0.1µF  [0402]  (hidden comment: GRM155R61C104KA88D)
C313  ValueDisplayed: 1500pF  [0805_HV]  (hidden comment: 08051C152KAT2A)
C400  ValueDisplayed: 1000pF  [0402]  (hidden comment: C1005C0G1E102J)
C401  ValueDisplayed: 22µF  [1210]  (hidden comment: C3225X5R1C226M)
C402  ValueDisplayed: 22µF  [1210]  (hidden comment: C3225X5R1C226M)
C403  ValueDisplayed: 22µF  [1210]  (hidden comment: C3225X5R1C226M)
C404  ValueDisplayed: 22µF  [1210]  (hidden comment: C3225X5R1C226M)
C405  ValueDisplayed: 22µF  [1210]  (hidden comment: C3225X5R1C226M)
C406  ValueDisplayed: 3300pF  [0402]  (hidden comment: C1005X7R1H332K)
C410  ValueDisplayed: 0.1µF  [0402]  (hidden comment: GRM155R61E104KA87D)
C411  ValueDisplayed: 10µF  [0603L]  (hidden comment: C0603C106M9PACTU)
C412  ValueDisplayed: 0.1µF  [0402]  (hidden comment: GRM155R61C104KA88D)
C413  ValueDisplayed: 1500pF  [0805_HV]  (hidden comment: 08051C152KAT2A)
C500  ValueDisplayed: 1000pF  [0402]  (hidden comment: C1005C0G1E102J)
C501  ValueDisplayed: 22µF  [1210]  (hidden comment: C3225X5R1C226M)
C502  ValueDisplayed: 22µF  [1210]  (hidden comment: C3225X5R1C226M)
C503  ValueDisplayed: 22µF  [1210]  (hidden comment: C3225X5R1C226M)
C504  ValueDisplayed: 22µF  [1210]  (hidden comment: C3225X5R1C226M)
C505  ValueDisplayed: 22µF  [1210]  (hidden comment: C3225X5R1C226M)
C506  ValueDisplayed: 3300pF  [0402]  (hidden comment: C1005X7R1H332K)
C510  ValueDisplayed: 0.1µF  [0402]  (hidden comment: GRM155R61E104KA87D)
C511  ValueDisplayed: 10µF  [0603L]  (hidden comment: C0603C106M9PACTU)
C512  ValueDisplayed: 0.1µF  [0402]  (hidden comment: GRM155R61C104KA88D)
C513  ValueDisplayed: 1500pF  [0805_HV]  (hidden comment: 08051C152KAT2A)
J11  CB35-36-CY  [CB35-36-CY]
J12  CB35-36-CY  [CB35-36-CY]
L100  FP1308R3-R21-R  ValueDisplayed: 210nH  Value2: 68A  [IND_FP1308]
L200  FP1308R3-R21-R  [IND_FP1308]
L300  FP1308R3-R21-R  [IND_FP1308]
L400  FP1308R3-R21-R  [IND_FP1308]
L500  FP1308R3-R21-R  [IND_FP1308]
R41  ValueDisplayed: 10  [0402]  (hidden comment: CRCW040210R0JNED)
R42  ValueDisplayed: 10  [0402]  (hidden comment: CRCW040210R0JNED)
R43  ValueDisplayed: 0.001  [2512]  (hidden comment: ERJ-M1WTF1M0U)
R101  ValueDisplayed: 150k  [0402]  (hidden comment: CRCW0402150KFKED)
R110  ValueDisplayed: 2.2  [0402]  (hidden comment: CRCW04022R20JNED)
R113  ValueDisplayed: 1.0  [1206]  (hidden comment: CRM1206-JW-1R0ELF)
R201  ValueDisplayed: 150k  [0402]  (hidden comment: CRCW0402150KFKED)
R210  value 2.2  [0402]  (hidden comment: CRCW04022R20JNED)
R213  value 1.0  [1206]  (hidden comment: CRM1206-JW-1R0ELF)
R301  ValueDisplayed: 150k  [0402]  (hidden comment: CRCW0402150KFKED)
R310  value 2.2  [0402]  (hidden comment: CRCW04022R20JNED)
R313  value 1.0  [1206]  (hidden comment: CRM1206-JW-1R0ELF)
R401  ValueDisplayed: 150k  [0402]  (hidden comment: CRCW0402150KFKED)
R410  value 2.2  [0402]  (hidden comment: CRCW04022R20JNED)
R413  value 1.0  [1206]  (hidden comment: CRM1206-JW-1R0ELF)
R501  ValueDisplayed: 150k  [0402]  (hidden comment: CRCW0402150KFKED)
R510  value 2.2  [0402]  (hidden comment: CRCW04022R20JNED)
R513  value 1.0  [1206]  (hidden comment: CRM1206-JW-1R0ELF)
RTN1  5016  [Testpoint_Keystone_Compact]  (value not drawn)
SW1  5015  [Testpoint_Keystone_Miniature]  (value not drawn)
SW2  5015  [Testpoint_Keystone_Miniature]  (value not drawn)
SW3  5015  [Testpoint_Keystone_Miniature]  (value not drawn)
SW4  5015  [Testpoint_Keystone_Miniature]  (value not drawn)
SW5  5015  [Testpoint_Keystone_Miniature]  (value not drawn)
TP199  5016  [Testpoint_Keystone_Compact]  (value not drawn)
U100  CSD95490Q5MC  [DMC0012A]
U200  CSD95490Q5MC  [DMC0012A]
U300  CSD95490Q5MC  [DMC0012A]
U400  CSD95490Q5MC  [DMC0012A]
U500  CSD95490Q5MC  [DMC0012A]
VIN  5000  [Keystone5000]  (value not drawn)
Vin_rtn  5001  [Keystone5001]  (value not drawn)

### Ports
A_pin11, CSP1 (out), CSP2 (out), CSP3 (out), CSP4 (out), CSP5 (out), CSPIN (out), PWM1 (in), PWM2 (in), PWM3 (in), PWM4 (in), PWM5 (in), TSEN, VIN_CSNIN (out), VREF

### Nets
5V: C111.1 C211.1 C311.1 C411.1 C511.1 U100.4(VDD) U200.4(VDD) U300.4(VDD) U400.4(VDD) U500.4(VDD)
GND: C11.2(-) C12.2(-) C13.2(-) C100.1 C101.2 C102.2 C103.2 C104.2 C105.2 C106.2 C111.2 C112.2 C200.1 C201.2 C202.2 C203.2 C204.2 C205.2 C206.2 C211.2 C212.2 C300.1 C301.2 C302.2 C303.2 C304.2 C305.2 C306.2 C311.2 C312.2 C400.1 C401.2 C402.2 C403.2 C404.2 C405.2 C406.2 C411.2 C412.2 C500.1 C501.2 C502.2 C503.2 C504.2 C505.2 C506.2 C511.2 C512.2 J12.1 R101.1 R113.1 R201.1 R213.1 R301.1 R313.1 R401.1 R413.1 R501.1 R513.1 RTN1.1 U100.13(PGND) U200.13(PGND) U300.13(PGND) U400.13(PGND) U500.13(PGND) Vin_rtn.1
Vin: C101.1 C102.1 C103.1 C104.1 C105.1 C106.1 C201.1 C202.1 C203.1 C204.1 C205.1 C206.1 C301.1 C302.1 C303.1 C304.1 C305.1 C306.1 C401.1 C402.1 C403.1 C404.1 C405.1 C406.1 C501.1 C502.1 C503.1 C504.1 C505.1 C506.1 R41.1 R43.1 TP199.1 U100.7(VIN) U200.7(VIN) U300.7(VIN) U400.7(VIN) U500.7(VIN)
Vin_P: C11.1(+) C12.1(+) C13.1(+) J11.1 R42.1 R43.2 VIN.1
Vout: L100.2 L200.2 L300.2 L400.2 L500.2 U100.5(VOS) U200.5(VOS) U300.5(VOS) U400.5(VOS) U500.5(VOS)
A_pin11: U100.11(EN/FCCM) U200.11(EN/FCCM) U300.11(EN/FCCM) U400.11(EN/FCCM) U500.11(EN/FCCM) ; port A_pin11
CSP1: U100.2(IOUT) ; port CSP1
CSP2: U200.2(IOUT) ; port CSP2
CSP3: U300.2(IOUT) ; port CSP3
CSP4: U400.2(IOUT) ; port CSP4
CSP5: U500.2(IOUT) ; port CSP5
CSPIN: R42.2 ; port CSPIN
PWM1: U100.10(PWM) ; port PWM1
PWM2: U200.10(PWM) ; port PWM2
PWM3: U300.10(PWM) ; port PWM3
PWM4: U400.10(PWM) ; port PWM4
PWM5: U500.10(PWM) ; port PWM5
TSEN: C100.2 C200.2 C300.2 C400.2 C500.2 U100.12(TAO/FAULT) U200.12(TAO/FAULT) U300.12(TAO/FAULT) U400.12(TAO/FAULT) U500.12(TAO/FAULT) ; port TSEN
VIN_CSNIN: R41.2 ; port VIN_CSNIN
VREF: C112.1 C212.1 C312.1 C412.1 C512.1 U100.1(REFIN) U200.1(REFIN) U300.1(REFIN) U400.1(REFIN) U500.1(REFIN) ; port VREF
NetC110_1: C110.1 U100.8(BOOTR)
NetC110_2: C110.2 R110.1
NetC113_1: C113.1 L100.1 SW1.1 U100.6(SW)
NetC113_2: C113.2 R113.2
NetC210_1: C210.1 U200.8(BOOTR)
NetC210_2: C210.2 R210.1
NetC213_1: C213.1 L200.1 SW2.1 U200.6(SW)
NetC213_2: C213.2 R213.2
NetC310_1: C310.1 U300.8(BOOTR)
NetC310_2: C310.2 R310.1
NetC313_1: C313.1 L300.1 SW3.1 U300.6(SW)
NetC313_2: C313.2 R313.2
NetC410_1: C410.1 U400.8(BOOTR)
NetC410_2: C410.2 R410.1
NetC413_1: C413.1 L400.1 SW4.1 U400.6(SW)
NetC413_2: C413.2 R413.2
NetC510_1: C510.1 U500.8(BOOTR)
NetC510_2: C510.2 R510.1
NetC513_1: C513.1 L500.1 SW5.1 U500.6(SW)
NetC513_2: C513.2 R513.2
NetR101_2: R101.2 U100.3(LSET)
NetR110_2: R110.2 U100.9(BOOT)
NetR201_2: R201.2 U200.3(LSET)
NetR210_2: R210.2 U200.9(BOOT)
NetR301_2: R301.2 U300.3(LSET)
NetR310_2: R310.2 U300.9(BOOT)
NetR401_2: R401.2 U400.3(LSET)
NetR410_2: R410.2 U400.9(BOOT)
NetR501_2: R501.2 U500.3(LSET)
NetR510_2: R510.2 U500.9(BOOT)

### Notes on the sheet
- Main Power Input
- (near R42) differential pair to controller
- 5 Power Stages for main Channel
- VIN = 4.5V to 13.2V
- XXXXXXXXXX

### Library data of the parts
C11-C13 = 35ZL470MEFC10X20: CAP, AL, 470 µF, 35 V, +/- 20%, TH; Manufacturer: Rubycon; Polarized: Y; CompType: Capacitor; Value: 470uF; U/M: EA; Cap_F: 0.00047; Tolerance_%: 20; Value1: Unknown; VDC_V: 35; Value2: 35V; TaMin_C: -40; TaMax_C: 105; Cap_Case: 10x20; AEC Category: Q200; AEC Qualified: N
C100 C200 C300 C400 C500 = C1005C0G1E102J: as C600 on sheet PMP20489_TPS53679controller&Ch2PS
C101-C105 C201-C205 C301-C305 C401-C405 C501-C505 = C3225X5R1C226M: as C601 on sheet PMP20489_TPS53679controller&Ch2PS
C106 C206 C306 C406 C506 = C1005X7R1H332K: as C606 on sheet PMP20489_TPS53679controller&Ch2PS
C110 C210 C310 C410 C510 = GRM155R61E104KA87D: as C610 on sheet PMP20489_TPS53679controller&Ch2PS
C111 C211 C311 C411 C511 = C0603C106M9PACTU: as C611 on sheet PMP20489_TPS53679controller&Ch2PS
C112 C212 C312 C412 C512 = GRM155R61C104KA88D: as C612 on sheet PMP20489_TPS53679controller&Ch2PS
C113 C213 C313 C413 C513 = 08051C152KAT2A: as C613 on sheet PMP20489_TPS53679controller&Ch2PS
J11 J12 = CB35-36-CY: Terminal 50A Lug; Manufacturer: Panduit; SymbolCreator: crossc; CompType: Screw Terminal; ContactFinish: Copper; Voltage_V: 600; Cert_CULUS: Y
L100 = FP1308-R21-R: Inductor, Shielded Drum Core, Metal Composite, 210 nH, 68 A, 0.2 ohm, SMD; Manufacturer: Coiltronics; Value: 210nH; Ind_H: 210.0E-9; Imax_A: 68; Irms: 68A @ 40C rise; Isat: 72A @ 20% inductance drop; DCR_ohm: 0.2; Value1: 0.2 ohm; AEC Category: Q200
L200 L300 L400 L500 = FP1308-R21-R: Inductor, Shielded Drum Core, Metal Composite, 210 nH, 68 A, 0.2 ohm, SMD; Manufacturer: Coiltronics; Value: 210nH; Ind_H: 210.0E-9; Imax_A: 68; Irms: 68A @ 40C rise; Isat: 72A @ 20% inductance drop; DCR_ohm: 0.2; Value1: 0.2 ohm; Value2: 68A; AEC Category: Q200
R41 R42 = CRCW040210R0JNED: RES, 10, 5%, 0.063 W, 0402; Manufacturer: Vishay-Dale; CompType: Resistor; Value: 10; Value_Code: 10R0; Tolerance_%: 5; Power_W: 0.063; Value2: 0.063W; VDC_V: 50; TempCo: 200 ppm/C; EIA_Code: E24; U/M: EA; SizeArea_mm2: 0.5; SizeX_mm: 1; SizeZ_mm: 0.6; AEC Category: Q200
R43 = ERJ-M1WTF1M0U: RES, 0.001, 1%, 1 W, 2512; Manufacturer: Panasonic; CompType: Resistor; Value: 0.001; Value_Code: 1L000; Tolerance_%: 1; Value2: 1W; TempCo: ppm/C; EIA_Code: E96; U/M: EA; SizeArea_mm2: 20.16; SizeX_mm: 6.3; SizeY_mm: 3.2; SizeZ_mm: 0.71; AEC Category: Q200
R101 R201 R301 R401 R501 = CRCW0402150KFKED: RES, 150 k, 1%, 0.063 W, 0402; Manufacturer: Vishay-Dale; CompType: Resistor; Value: 150k; Res_ohm: 150000; Tolerance_%: 1; Power_W: 0.063; Value2: 0.063W; VDC_V: 50; TempCo: 100 ppm/C; EIA_Code: E96; U/M: EA; SizeArea_mm2: 0.5; SizeZ_mm: 0.6; AEC Category: Q200
R110 = CRCW04022R20JNED: RES, 2.2, 5%, 0.063 W, 0402; Manufacturer: Vishay-Dale; CompType: Resistor; Value: 2.2; Value_Code: 2R20; Tolerance_%: 5; Power_W: 0.063; Value2: 0.063W; VDC_V: 50; TempCo: 200 ppm/C; EIA_Code: E24; U/M: EA; SizeArea_mm2: 0.5; SizeX_mm: 1; SizeZ_mm: 0.6; AEC Category: Q200
R113 = CRM1206-JW-1R0ELF: RES, 1.0, 5%, 0.5 W, 1206; Manufacturer: Bourns; CompType: Resistor; Value: 1.0; Res_ohm: 1; Value_Code: 1R00; Tolerance_%: 5; Power_W: 0.5; Value2: 0.5W; TempCo: 150 ppm/C; EIA_Code: E24; U/M: EA; SizeArea_mm2: 5.12; SizeX_mm: 3.2; SizeY_mm: 1.6; SizeZ_mm: 1.35; AEC Category: Q200
R210 R310 R410 R510 = CRCW04022R20JNED: as R610 on sheet PMP20489_TPS53679controller&Ch2PS
R213 R313 R413 R513 = CRM1206-JW-1R0ELF: as R613 on sheet PMP20489_TPS53679controller&Ch2PS
RTN1 TP199 = 5016: as RTN6 on sheet PMP20489_TPS53679controller&Ch2PS
SW1-SW5 = 5015: as SW6 on sheet PMP20489_TPS53679controller&Ch2PS
U100 U200 U300 U400 U500 = CSD95490Q5MC: as U600 on sheet PMP20489_TPS53679controller&Ch2PS
VIN = 5000: as TP1 on sheet PMP20489_TPS53679controller&Ch2PS
Vin_rtn = 5001: Test Point, Miniature, Black, TH; Manufacturer: Keystone; CompType: Test Point Loop; ContactFinish: Silver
